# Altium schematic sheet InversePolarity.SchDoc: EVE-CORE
size A4; Organization: Ingenia Motion Control; Address1: Carrer Avila, 124, 2B; Address2: 08018 Barcelona Spain; Address3: www.ingeniamc.com; Address4: www.ingeniamc.com; Documentation: https://doc.ingeniamc.com/x/coAZBg
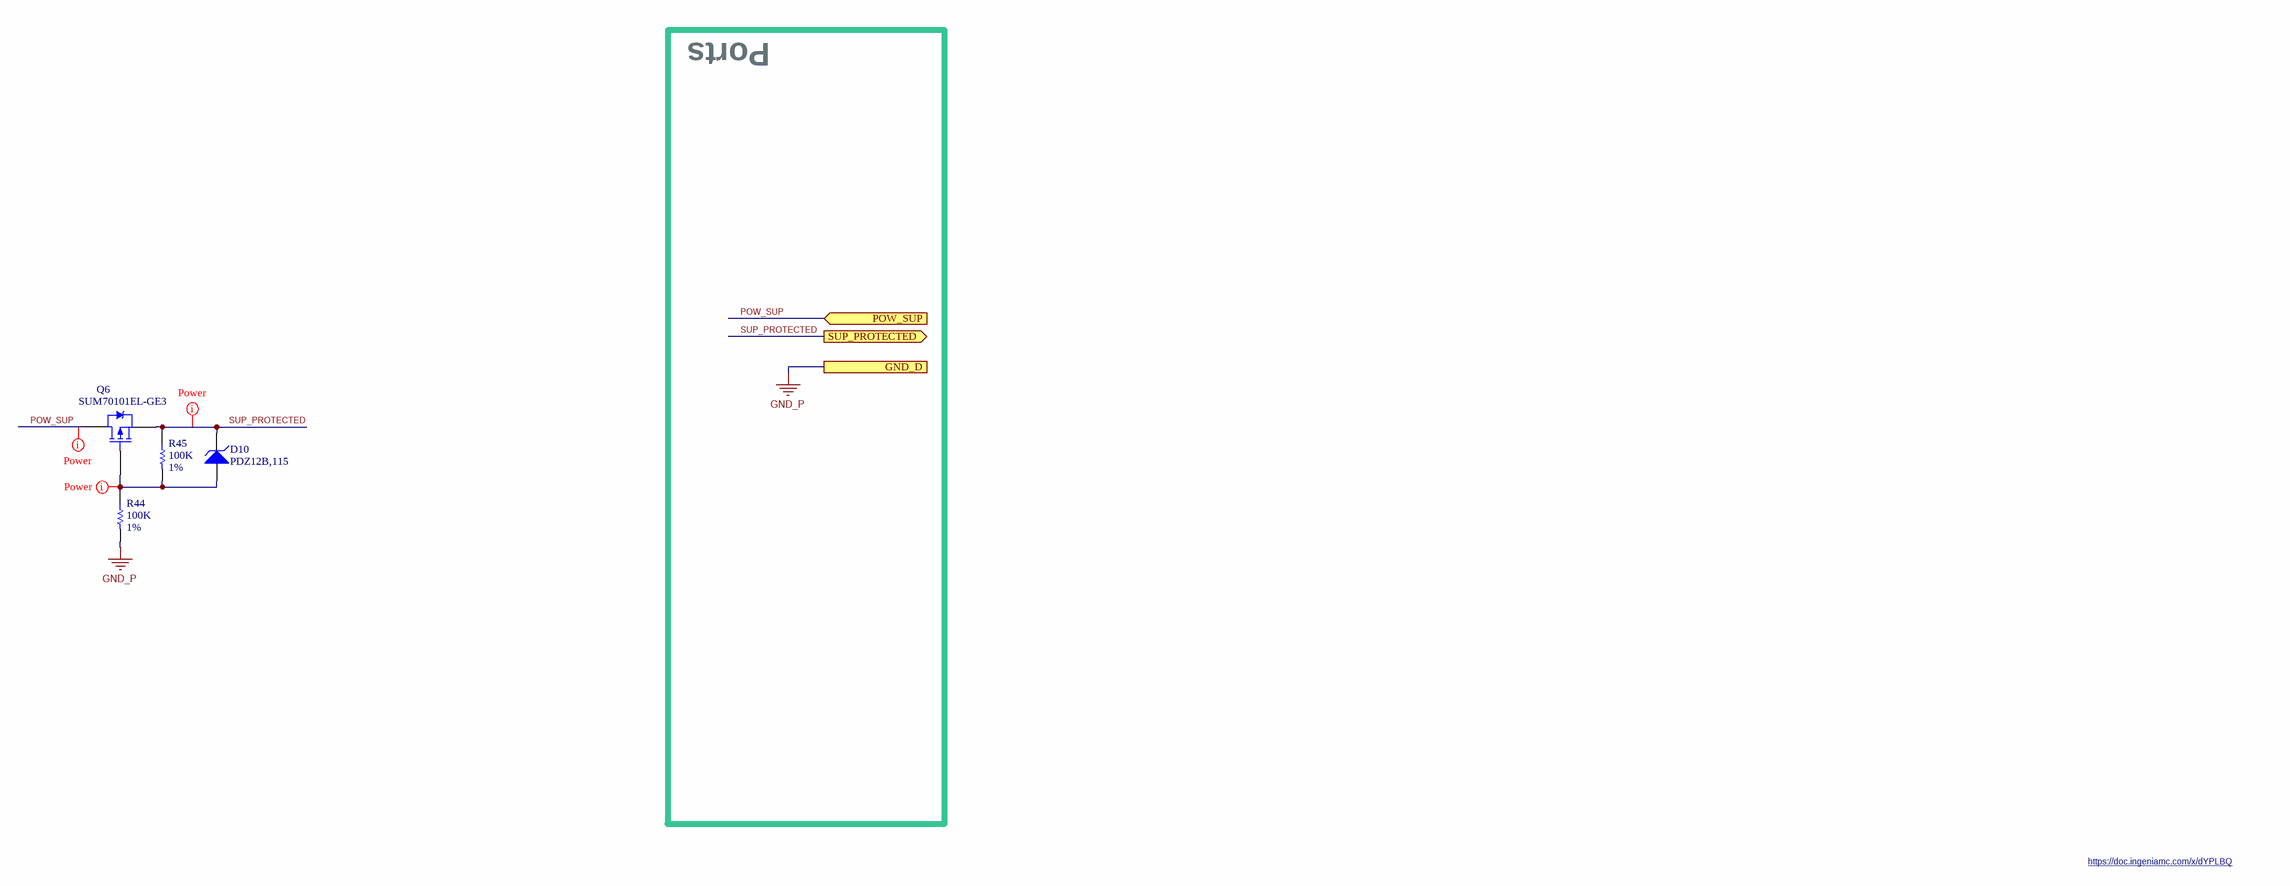
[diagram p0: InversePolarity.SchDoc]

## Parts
D10  PDZ12B,115  [SOD-323]
Q6  SUM70101EL-GE3  [D2PAK/TO263-3N]
R44  value 100K  Tolerance: 1%  [R_0603]  (hidden comment: R_0603HV--100K--1%)
R45  value 100K  Tolerance: 1%  [R_0603]  (hidden comment: R_0603HV--100K--1%)

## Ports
GND_D, POW_SUP (in), SUP_PROTECTED (out)

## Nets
GND_P: R44.2 ; port GND_D
POW_SUP: Q6.4(D) ; port POW_SUP
SUP_PROTECTED: D10.2(K) Q6.3(S) R45.1 ; port SUP_PROTECTED
NetD10_1: D10.1(A) Q6.1(G) R44.1 R45.2

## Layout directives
net class Power: NetD10_1, POW_SUP, SUP_PROTECTED

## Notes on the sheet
- Ports
- https://doc.ingeniamc.com/x/dYPLBQ

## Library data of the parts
D10 = PDZ12B,115: Diode Zener 12V 0.4W 400mW 2% SOD-323; ManufacturerName: NXP; IsPreferred: 1; IsGeneric: 0; IngeniaID: 1529; TemperatureMaxC: 150; TemperatureMinC: -65
Q6 = SUM70101EL-GE3: P-channel MOSFET, 100 V, 120 A, 10.1 mOhm; ManufacturerName: Vishay; Value: 100V; IsPreferred: 0; IngeniaID: 4538
R44 R45 = R_0603HV[[/\]]100K[[/\]]1%: RESISTOR, 0603, 100K, 150 V, 1%, 1/4W; ManufacturerName: Panasonic; ManufacturerPN: ERJPA3F1003V; IsPreferred: 0; IngeniaID: 2568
